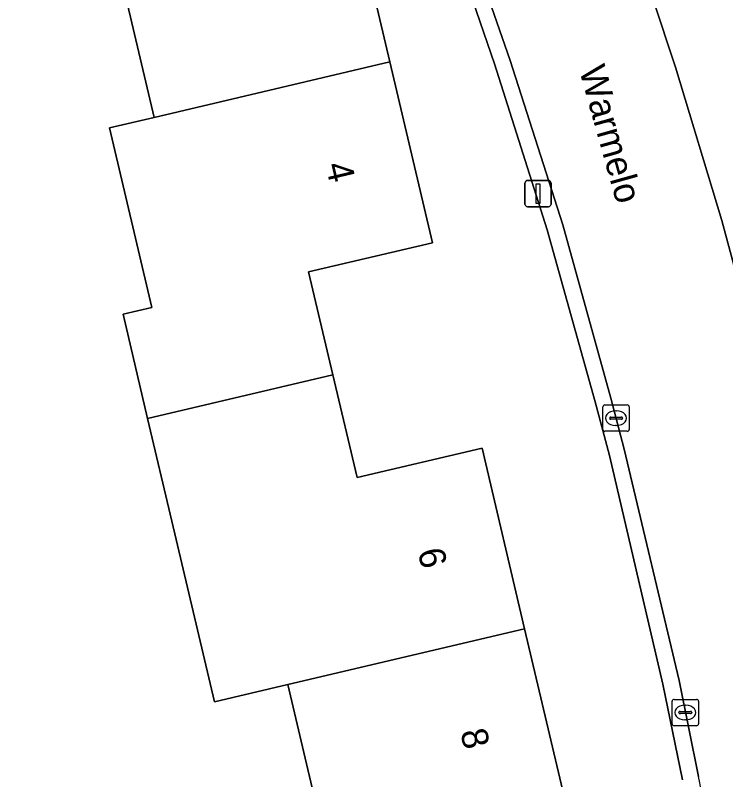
# Model space of a CAD drawing. Extents: x 157648 to 158502, y 379212 to 380938.
# Drawn here: x 158252.3 to 158279.25, y 380614.21 to 380643.22 of the extents above; entities that cross this region are included whole.
import ezdxf

# ---------------------------------------------------------------- set-up
doc = ezdxf.new("R2010")
doc.units = 0
for name, color, linetype in [('IMGEO_Erf', 7, 'Continuous'), ('IMGEO_Kolk', 7, 'Continuous'), ('IMGEO_Lichtmast', 7, 'Continuous'), ('IMGEO_Openbare_ruimte_label', 7, 'Continuous'), ('IMGEO_Pand', 7, 'Continuous'), ('IMGEO_Pand_nummerreeks', 7, 'Continuous'), ('IMGEO_Rijbaan_lokaal_open', 7, 'Continuous'), ('IMGEO_Voetpad_open', 7, 'Continuous')]:
    doc.layers.add(name, color=color, linetype=linetype)

msp = doc.modelspace()

# ---------------------------------------------------------------- linework, layer by layer
at = {"layer": 'IMGEO_Erf'}
for points in [[(158264.89, 380648.323), (158266.508, 380641.458), (158268.126, 380634.592), (158263.426, 380633.484), (158264.346, 380629.582), (158265.266, 380625.678), (158270.005, 380626.795), (158271.62, 380619.942), (158273.235, 380613.091), (158268.359, 380611.941), (158269.253, 380608.147), (158262.371, 380606.525), (158261.446, 380610.453), (158264.213, 380611.105), (158262.63, 380617.823), (158259.849, 380617.168), (158258.232, 380624.028), (158257.314, 380627.924), (158256.383, 380631.874), (158257.477, 380632.132), (158255.871, 380638.953), (158257.561, 380639.351), (158255.967, 380646.114)], [(158277.607, 380614.209), (158276.868, 380617.835), (158274.835, 380626.514), (158274.294, 380628.549), (158272.481, 380635.085), (158270.472, 380641.386), (158268.423, 380647.352)]]:
    msp.add_lwpolyline(points, dxfattribs=at)
at = {"layer": 'IMGEO_Kolk'}
for p, q in [((158274.588, 380627.507), (158274.588, 380628.359)), ((158274.663, 380628.433), (158275.515, 380628.433)), ((158275.076, 380628.213), (158275.101, 380628.213)), ((158275.589, 380628.359), (158275.589, 380627.507)), ((158274.847, 380627.927), (158274.847, 380627.939)), ((158275.285, 380627.89), (158274.887, 380627.89)), ((158274.89, 380627.976), (158275.288, 380627.976)), ((158275.331, 380627.939), (158275.331, 380627.927)), ((158275.099, 380627.653), (158275.074, 380627.653)), ((158275.515, 380627.433), (158274.663, 380627.433)), ((158277.217, 380616.333), (158277.217, 380617.185)), ((158277.292, 380617.259), (158278.144, 380617.259)), ((158278.218, 380617.185), (158278.218, 380616.333)), ((158277.705, 380617.039), (158277.73, 380617.039)), ((158277.476, 380616.753), (158277.476, 380616.765)), ((158277.914, 380616.716), (158277.516, 380616.716)), ((158277.519, 380616.802), (158277.917, 380616.802)), ((158277.96, 380616.765), (158277.96, 380616.753)), ((158278.144, 380616.259), (158277.292, 380616.259)), ((158277.728, 380616.479), (158277.703, 380616.479))]:
    msp.add_line(p, q, dxfattribs=at)
for points in [[(158274.588, 380627.507), (158274.588, 380628.359)], [(158274.663, 380628.433), (158275.515, 380628.433)], [(158275.589, 380628.359), (158275.589, 380627.507)], [(158275.515, 380627.433), (158274.663, 380627.433)], [(158277.217, 380616.333), (158277.217, 380617.185)], [(158277.292, 380617.259), (158278.144, 380617.259)], [(158278.218, 380617.185), (158278.218, 380616.333)], [(158278.144, 380616.259), (158277.292, 380616.259)]]:
    msp.add_lwpolyline(points, dxfattribs=at)
for centre, radius, start, end in [((158274.665, 380628.357), 0.0765, 91.552, 178.448), ((158274.665, 380628.357), 0.0765, 91.552, 178.448), ((158275.513, 380628.357), 0.0765, 1.552, 88.448), ((158275.513, 380628.357), 0.0765, 1.552, 88.448), ((158274.887, 380627.936), 0.0403, 85.8775, 175.7526), ((158274.884, 380627.926), 0.0366, 178.938, 274.7102), ((158275.288, 380627.933), 0.043, 264.8664, 352.4533), ((158275.292, 380627.938), 0.0386, 1.7309, 96.639), ((158274.665, 380627.509), 0.0765, 181.552, 268.448), ((158274.665, 380627.509), 0.0765, 181.552, 268.448), ((158275.513, 380627.509), 0.0765, 271.552, 358.448), ((158275.513, 380627.509), 0.0765, 271.552, 358.448), ((158277.294, 380617.183), 0.0765, 91.552, 178.448), ((158277.294, 380617.183), 0.0765, 91.552, 178.448), ((158278.142, 380617.183), 0.0765, 1.552, 88.448), ((158278.142, 380617.183), 0.0765, 1.552, 88.448), ((158277.516, 380616.762), 0.0403, 85.8775, 175.7526), ((158277.513, 380616.752), 0.0366, 178.938, 274.7102), ((158277.917, 380616.759), 0.043, 264.8664, 352.4533), ((158277.921, 380616.764), 0.0386, 1.7309, 96.639), ((158277.294, 380616.335), 0.0765, 181.552, 268.448), ((158277.294, 380616.335), 0.0765, 181.552, 268.448), ((158278.142, 380616.335), 0.0765, 271.552, 358.448), ((158278.142, 380616.335), 0.0765, 271.552, 358.448)]:
    msp.add_arc(centre, radius, start, end, dxfattribs=at)
for centre, major_axis, ratio, start_param, end_param in [((158275.075, 380627.933), (-0.387, 0.002), 0.722429, 4.712389, 7.853982), ((158275.1, 380627.933), (-0.39, 0.002), 0.717154, 1.570796, 4.712389), ((158277.704, 380616.759), (-0.387, 0.002), 0.722429, 4.712389, 7.853982), ((158277.729, 380616.759), (-0.39, 0.002), 0.717154, 1.570796, 4.712389)]:
    msp.add_ellipse(centre, major_axis=major_axis, ratio=ratio, start_param=start_param, end_param=end_param, dxfattribs=at)
at = {"layer": 'IMGEO_Lichtmast'}
for p, q in [((158271.632, 380636.057), (158271.632, 380636.857)), ((158271.632, 380636.857), (158271.632, 380636.057)), ((158271.732, 380636.957), (158272.522, 380636.957)), ((158272.522, 380636.957), (158271.732, 380636.957)), ((158272.622, 380636.857), (158272.622, 380636.057)), ((158272.622, 380636.057), (158272.622, 380636.857)), ((158272.522, 380635.957), (158271.732, 380635.957)), ((158271.732, 380635.957), (158272.522, 380635.957))]:
    msp.add_line(p, q, dxfattribs=at)
msp.add_lwpolyline([(158272.052, 380636.832), (158272.202, 380636.832), (158272.202, 380636.082), (158272.052, 380636.082), (158272.052, 380636.832)], dxfattribs=at)
for centre, start, end in [((158271.732, 380636.857), 90, 180), ((158271.732, 380636.857), 90, 180), ((158272.522, 380636.857), 0, 90), ((158272.522, 380636.857), 360, 90), ((158271.732, 380636.057), 180, 270), ((158271.732, 380636.057), 180, 270), ((158272.522, 380636.057), 270, 0), ((158272.522, 380636.057), 270, 0)]:
    msp.add_arc(centre, 0.1, start, end, dxfattribs=at)
at = {"layer": 'IMGEO_Pand'}
for points in [[(158262.407, 380651.804), (158259.217, 380651.052), (158252.295, 380649.421), (158253.226, 380645.468), (158255.967, 380646.114), (158257.561, 380639.351), (158266.508, 380641.458), (158264.89, 380648.323), (158263.315, 380647.952)], [(158257.314, 380627.924), (158264.346, 380629.582), (158263.426, 380633.484), (158268.126, 380634.592), (158266.508, 380641.458), (158257.561, 380639.351), (158255.871, 380638.953), (158257.477, 380632.132), (158256.383, 380631.874)], [(158257.314, 380627.924), (158258.232, 380624.028), (158259.849, 380617.168), (158262.63, 380617.823), (158271.62, 380619.942), (158270.005, 380626.795), (158265.266, 380625.678), (158264.346, 380629.582)], [(158271.62, 380619.942), (158262.63, 380617.823), (158264.213, 380611.105), (158261.446, 380610.453), (158262.371, 380606.525), (158269.253, 380608.147), (158268.359, 380611.941), (158273.235, 380613.091)]]:
    msp.add_lwpolyline(points, close=True, dxfattribs=at)
at = {"layer": 'IMGEO_Rijbaan_lokaal_open'}
for points in [[(158281.301, 380627.252), (158279.102, 380635.44), (158277.35, 380641.254), (158275.628, 380646.459), (158269.134, 380664.006), (158269.099, 380664.106)], [(158264.905, 380658.157), (158265.25, 380657.252), (158266.856, 380653.04), (158268.233, 380649.501), (158268.951, 380647.635), (158271.067, 380641.515), (158273.069, 380635.27), (158274.89, 380628.688), (158275.399, 380626.75), (158277.479, 380617.972), (158278.213, 380614.328)]]:
    msp.add_lwpolyline(points, dxfattribs=at)
msp.add_arc((158253.625, 380608.956), 25.168, 3.6133, 12.3247, dxfattribs=at)
at = {"layer": 'IMGEO_Voetpad_open'}
for points in [[(158269.099, 380664.106), (158269.134, 380664.006), (158275.628, 380646.459), (158277.35, 380641.254), (158279.102, 380635.44), (158281.301, 380627.252), (158283.092, 380619.448), (158284.585, 380612.128)], [(158268.951, 380647.635), (158268.233, 380649.501), (158266.856, 380653.04), (158265.25, 380657.252), (158264.64, 380657.11), (158266.359, 380652.693), (158268.423, 380647.352), (158270.472, 380641.386), (158272.481, 380635.085), (158274.294, 380628.549), (158274.835, 380626.514), (158276.868, 380617.835), (158277.607, 380614.209)], [(158278.213, 380614.328), (158277.479, 380617.972), (158275.399, 380626.75), (158274.89, 380628.688), (158273.069, 380635.27), (158271.067, 380641.515), (158268.951, 380647.635)]]:
    msp.add_lwpolyline(points, dxfattribs=at)
msp.add_arc((158253.625, 380608.956), 25.168, 3.6133, 12.3247, dxfattribs=at)

# ---------------------------------------------------------------- texts
at = {"layer": 'IMGEO_Openbare_ruimte_label'}
msp.add_text('Warmelo', height=1, rotation=285.6621, dxfattribs=at).set_placement((158273.681, 380641.162))
at = {"layer": 'IMGEO_Pand_nummerreeks'}
for s, rotation, p in [('4', 283.261, (158264.061, 380637.541)), ('6', 283.2624, (158267.557, 380622.884)), ('8', 283.2624, (158269.173, 380616.028))]:
    msp.add_text(s, height=1, rotation=rotation, dxfattribs=at).set_placement(p)

doc.saveas('drawing.dxf')
